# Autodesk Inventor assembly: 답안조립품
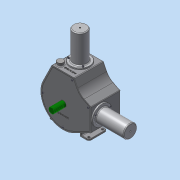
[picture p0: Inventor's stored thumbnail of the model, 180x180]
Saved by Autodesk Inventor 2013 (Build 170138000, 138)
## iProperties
Created: 2017-05
Part Number: 답안조립품
Document SubType Name: Assembly
Designer: dgall
Mass: 2156.82 g
Surface Area: 4005.96 cm^2
Volume: 952.79 cm^3
Density: 2.26369 g/cm^3
Author: dgall
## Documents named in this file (13)
- C:\Users\dgall\Desktop\370507V1013\답안조립품.iam
- C:\Users\dgall\Desktop\370507V1013\본체.ipt
- C:\Users\dgall\Desktop\370507V1013\앞커버.ipt
- C:\Users\dgall\Desktop\370507V1013\축.ipt
- C:\Users\dgall\Desktop\370507V1013\베어링 20 x 37 x 9.ipt
- C:\Users\dgall\Desktop\370507V1013\커넥팅로드.ipt
- C:\Users\dgall\Desktop\370507V1013\커넥팅로드 캡.ipt
- C:\Users\dgall\Desktop\370507V1013\측정게이지.ipt
- C:\Users\dgall\Desktop\370507V1013\실린더.ipt
- C:\Users\dgall\Desktop\370507V1013\피스톤.ipt
- C:\Users\dgall\Desktop\370507V1013\피스톤 핀.ipt
- C:\Users\dgall\Desktop\370507V1013\볼트 M3 x 12.ipt
- C:\Users\dgall\Desktop\370507V1013\너트 M3.ipt
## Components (4 placed, 2 different names)
1. 피스톤:1
2. 피스톤:2
3. 피스톤 핀:1
4. 피스톤 핀:2
